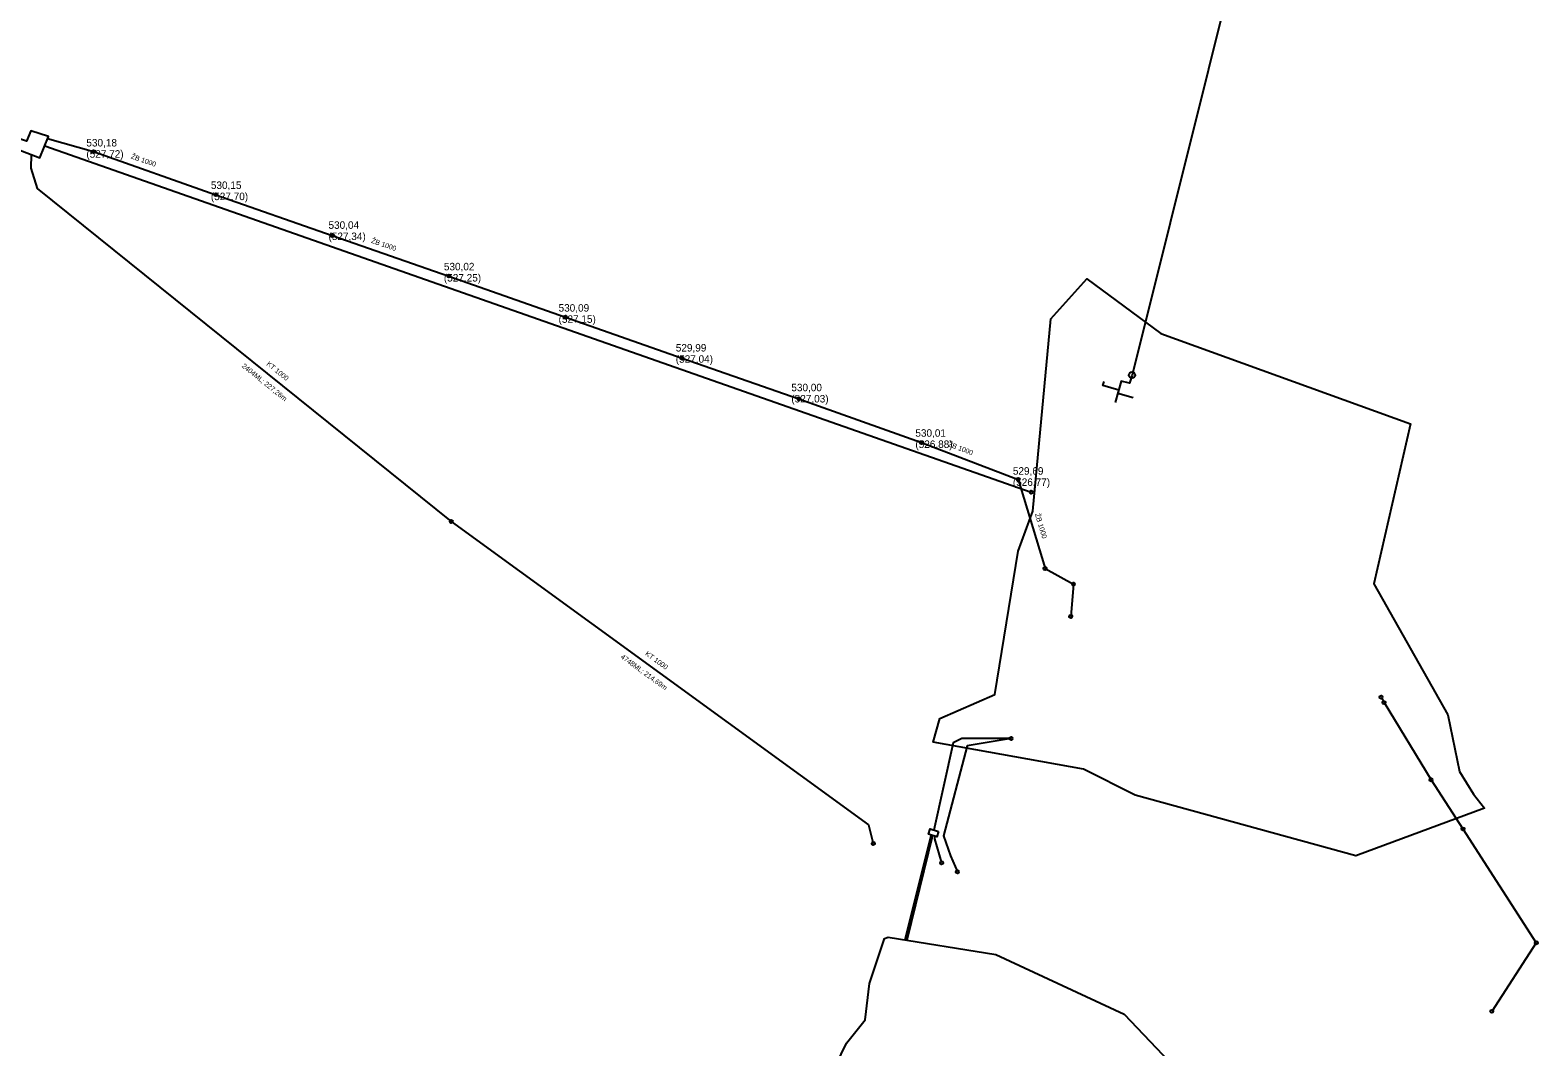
# Model space of a CAD drawing. Extents: x -867696 to -865033, y -1042522 to -1039817.
# Drawn here: x -865929 to -865324, y -1042001 to -1041593 of the extents above; entities that cross this region are included whole.
import ezdxf

# ---------------------------------------------------------------- set-up
doc = ezdxf.new("R2010")
doc.units = 0
for name, color, linetype in [('KN - arealova destova', 7, 'Continuous'), ('KN - COV', 7, 'Continuous'), ('KN - jednotna', 7, 'Continuous'), ('KN - jina', 7, 'Continuous'), ('KN - ostatni', 7, 'Continuous'), ('KN - popis material', 7, 'Continuous'), ('KN - popis ostatni', 7, 'Continuous'), ('KN - popis usek delka', 7, 'Continuous'), ('KN - sachta komora', 7, 'Continuous'), ('Level 1', 7, 'Continuous'), ('V - pripojka', 7, 'Continuous'), ('V - rozvadeci', 7, 'Continuous'), ('V - sachta', 7, 'Continuous')]:
    doc.layers.add(name, color=color, linetype=linetype)

# ---------------------------------------------------------------- blocks, each defined once
blk = doc.blocks.new('100.M')
at = {"layer": 'Level 1'}
blk.add_circle((0, 0), 1.27, dxfattribs=at)
blk = doc.blocks.new('143')
at = {"layer": 'Level 1'}
blk.add_circle((0, 0), 1.27, dxfattribs=at)

msp = doc.modelspace()

# ---------------------------------------------------------------- linework, layer by layer
at = {"layer": 'KN - arealova destova'}
for points in [[(-865386.458, -1041860.384), (-865385.26, -1041862.571)], [(-865385.26, -1041862.571), (-865366.405, -1041893.56)], [(-865366.405, -1041893.56), (-865353.578, -1041913.269)], [(-865353.578, -1041913.269), (-865324.17, -1041958.946)], [(-865324.17, -1041958.946), (-865342.002, -1041986.476)]]:
    msp.add_lwpolyline(points, dxfattribs=at)
at = {"layer": 'KN - COV'}
msp.add_lwpolyline([(-865518.919, -1041708.509), (-865504.528, -1041692.553), (-865474.807, -1041714.453), (-865374.695, -1041750.744), (-865389.399, -1041814.878), (-865359.678, -1041867.437), (-865354.986, -1041890.275), (-865349.354, -1041899.348), (-865344.974, -1041904.979), (-865396.595, -1041924.063), (-865485.131, -1041899.66), (-865505.779, -1041889.336), (-865566.12, -1041878.426), (-865563.539, -1041868.884), (-865541.444, -1041859.303), (-865532.059, -1041801.738), (-865526.115, -1041785.783), (-865518.919, -1041708.509)], dxfattribs=at)
at = {"layer": 'KN - jednotna'}
for points in [[(-865922.65, -1041639.124), (-865526.819, -1041778.108)], [(-865921.52, -1041636.185), (-865903.069, -1041641.449)], [(-865903.069, -1041641.449), (-865853.948, -1041658.728)], [(-865853.948, -1041658.728), (-865807.298, -1041675.147)], [(-865807.298, -1041675.147), (-865760.487, -1041691.368)], [(-865760.487, -1041691.368), (-865713.718, -1041707.888)], [(-865713.718, -1041707.888), (-865666.939, -1041724.308)], [(-865666.939, -1041724.308), (-865620.019, -1041740.608)], [(-865620.019, -1041740.608), (-865570.798, -1041758.239)], [(-865570.798, -1041758.239), (-865532.079, -1041772.967)], [(-865532.079, -1041772.967), (-865521.266, -1041808.777)], [(-865521.266, -1041808.777), (-865509.846, -1041815.034)], [(-865509.846, -1041815.034), (-865510.952, -1041827.987)]]:
    msp.add_lwpolyline(points, dxfattribs=at)
at = {"layer": 'KN - jina'}
for points in [[(-865928.038, -1041642.615), (-865928.255, -1041648.064), (-865925.722, -1041656.207), (-865759.542, -1041789.895)], [(-865759.542, -1041789.895), (-865592.142, -1041911.62), (-865590.195, -1041919.085)], [(-865534.92, -1041876.971), (-865554.701, -1041876.94), (-865558.143, -1041878.66), (-865565.868, -1041913.735)], [(-865534.92, -1041876.971), (-865552.472, -1041879.951), (-865562.014, -1041916.085), (-865559.199, -1041924.063), (-865556.461, -1041930.476)], [(-865567.028, -1041915.696), (-865577.566, -1041957.802)], [(-865566.42, -1041915.886), (-865576.786, -1041957.926)], [(-865565.443, -1041916.192), (-865565.651, -1041917.297), (-865562.757, -1041926.839)]]:
    msp.add_lwpolyline(points, dxfattribs=at)
at = {"layer": 'KN - ostatni'}
msp.add_lwpolyline([(-865613.907, -1042025.983), (-865600.97, -1041999.289), (-865593.409, -1041989.906), (-865591.678, -1041975.238), (-865585.756, -1041957.199), (-865584.207, -1041956.744), (-865541.083, -1041963.613), (-865489.55, -1041987.662), (-865432.701, -1042047.427)], dxfattribs=at)
at = {"layer": 'KN - sachta komora'}
for points in [[(-865938.317, -1041634.37), (-865939.634, -1041638.155), (-865924.658, -1041643.915), (-865922.848, -1041639.636), (-865921.202, -1041635.358), (-865928.278, -1041633.054), (-865930.006, -1041637.25), (-865938.317, -1041634.37)], [(-865564.009, -1041914.325), (-865564.731, -1041916.414), (-865568.037, -1041915.381), (-865567.333, -1041913.269), (-865564.009, -1041914.325)]]:
    msp.add_lwpolyline(points, dxfattribs=at)
at = {"layer": 'V - pripojka'}
for points in [[(-865486.37, -1041731.094), (-865487.361, -1041734.359), (-865490.678, -1041733.58), (-865493.149, -1041742.11)], [(-865491.726, -1041737.197), (-865498.125, -1041735.273), (-865497.617, -1041733.716)], [(-865492.07, -1041738.386), (-865485.905, -1041740.113)]]:
    msp.add_lwpolyline(points, dxfattribs=at)
at = {"layer": 'V - rozvadeci'}
msp.add_lwpolyline([(-865425.167, -1041485.894), (-865486.37, -1041731.094)], dxfattribs=at)

# ---------------------------------------------------------------- block references
at = {"layer": 'KN - sachta komora'}
for p, xscale, yscale, rotation in [((-865903.069, -1041641.449), 0.517562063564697, 0.5175620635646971, 157.49634583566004), ((-865853.948, -1041658.728), 0.5158478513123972, 0.5158478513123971, 156.4154111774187), ((-865807.298, -1041675.147), 0.5158478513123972, 0.5158478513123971, 156.4154111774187), ((-865760.487, -1041691.368), 0.5158478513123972, 0.5158478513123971, 156.4154111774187), ((-865713.718, -1041707.888), 0.5158478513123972, 0.5158478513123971, 156.4154111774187), ((-865666.939, -1041724.308), 0.5158478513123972, 0.5158478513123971, 156.4154111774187), ((-865620.019, -1041740.608), 0.5158478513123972, 0.5158478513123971, 156.4154111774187), ((-865570.798, -1041758.239), 0.5148474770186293, 0.5148474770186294, 155.86620948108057), ((-865532.079, -1041772.967), 0.50000000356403, 0.50000000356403, -46.99999943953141), ((-865526.819, -1041778.108), 0.5158478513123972, 0.5158478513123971, 156.4154111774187), ((-865759.542, -1041789.895), 0.49999999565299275, 0.4999999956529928, 142.99999806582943), ((-865521.266, -1041808.777), 0.5000000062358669, 0.5000000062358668, -49.99999868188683), ((-865509.846, -1041815.034), 0.5000000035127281, 0.5000000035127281, 118.99999892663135), ((-865510.952, -1041827.987), 0.5000000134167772, 0.5000000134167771, -93.99999971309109), ((-865386.458, -1041860.384), 0.5000000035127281, 0.5000000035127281, 118.99999892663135), ((-865385.26, -1041862.571), 0.5000000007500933, 0.5000000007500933, -59.00000017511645), ((-865534.92, -1041876.971), 0.500000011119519, 0.5000000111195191, 94.99999998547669), ((-865366.405, -1041893.56), 0.4999999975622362, 0.4999999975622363, -56.999998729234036), ((-865353.578, -1041913.269), 0.4999999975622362, 0.4999999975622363, -56.999998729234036), ((-865590.195, -1041919.085), 0.499999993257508, 0.4999999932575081, -74.99999987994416), ((-865562.757, -1041926.839), 0.49999998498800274, 0.49999998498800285, -73.00000033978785), ((-865556.461, -1041930.476), 0.49999998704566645, 0.49999998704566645, -65.99999939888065), ((-865324.17, -1041958.946), 0.5, 0.5, 90), ((-865342.002, -1041986.476), 0.4999999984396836, 0.49999999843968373, -122.00000027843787)]:
    msp.add_blockref('100.M', p, dxfattribs=dict(at, xscale=xscale, yscale=yscale, rotation=rotation))
at = {"layer": 'V - sachta', "xscale": 1.0000000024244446, "yscale": 1.0000000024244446, "rotation": -104.00000032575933}
msp.add_blockref('143', (-865486.37, -1041731.094), dxfattribs=at)

# ---------------------------------------------------------------- texts
at = {"layer": 'KN - popis material'}
for s, rotation, p in [('ŽB 1000', 340.62, (-865888.246, -1041644.119)), ('ŽB 1000', 340.89, (-865791.84, -1041677.964)), ('KT 1000', 321.18, (-865833.881, -1041727.01)), ('ŽB 1000', 339.17, (-865560.367, -1041759.638)), ('ŽB 1000', 286.8, (-865525.351, -1041786.942)), ('KT 1000', 323.98, (-865681.937, -1041843.359))]:
    msp.add_text(s, height=2, rotation=rotation, dxfattribs=at).set_placement(p)
at = {"layer": 'KN - popis ostatni'}
for s, p in [('530,18 ', (-865905.949, -1041639.379)), ('(527,72)', (-865905.949, -1041643.879)), ('530,15 ', (-865855.988, -1041656.418)), ('(527,70)', (-865855.988, -1041660.918)), ('530,04 ', (-865808.788, -1041672.427)), ('(527,34)', (-865808.788, -1041676.927)), ('530,02 ', (-865762.497, -1041689.078)), ('(527,25)', (-865762.497, -1041693.578)), ('530,09 ', (-865716.468, -1041705.648)), ('(527,15)', (-865716.468, -1041710.148)), ('529,99 ', (-865669.439, -1041721.668)), ('(527,04)', (-865669.439, -1041726.168)), ('530,00 ', (-865623.069, -1041737.608)), ('(527,03)', (-865623.069, -1041742.108)), ('530,01 ', (-865573.308, -1041755.859)), ('(526,88)', (-865573.308, -1041760.359)), ('529,69 ', (-865534.189, -1041771.087)), ('(526,77)', (-865534.189, -1041775.587))]:
    msp.add_text(s, height=3, dxfattribs=at).set_placement(p)
at = {"layer": 'KN - popis usek delka'}
for s, rotation, p in [('2404ML; 227,26m', 321.18, (-865843.753, -1041727.795)), ('4748ML; 214,69m', 323.98, (-865691.76, -1041844.624))]:
    msp.add_text(s, height=1.99999, rotation=rotation, dxfattribs=at).set_placement(p)

doc.saveas('drawing.dxf')
